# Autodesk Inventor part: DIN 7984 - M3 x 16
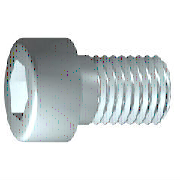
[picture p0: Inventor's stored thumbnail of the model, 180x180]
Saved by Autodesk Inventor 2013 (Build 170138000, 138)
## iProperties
Created: 2012-02
Part Number: DIN 7984 - M3 x 16
Material: Stahl, weich
Description: Zylinderkopfschraube
Document SubType Name: Modeling
Standard: DIN 7984
Designer: rYan
Standard Revision: 1985
Standards Organization: DIN
Language: de-DE
Size Designation: M3 x 16
Categories: <MemberInstance><Categories><Category DisplayName="Verbindungselemente" InternalName="e4da775c-781d-43d5-af7c-5136215cf5a6" Mnemonic="FSTN"><Category DisplayNam
Density: 7.86 g/cm^3
Mass: 1.20882 g
Surface Area: 2.39725 cm^2
Volume: 0.153794 cm^3
IsCustomPart: 0
Author: rYan
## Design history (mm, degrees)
sketch "Skizze1"
  geometry: L1 (0.167, 0)-(16, 0); L2 (16, 0)-(16, 1.5); L3 (16, 1.5)-(1.5, 1.5); L4 (1.5, 1.5)-(1.193, 1.5); L5 (1.193, 1.5)-(0, 1.5); L6 (0, 1.5)-(0, 2.75); L7 (0, 2.75)-(-2, 2.75); L8 (-2, 2.75)-(-2, 1.155); L9 (-2, 1.155)-(-0.5, 1.155); L10 (-0.5, 1.155)-(0.167, 0); L11 (-5.6, 0)-(19.6, 0) reference; L12 (0, -0.55)-(0, 3.3) reference; L13 (1.5, 1.5)-(0, 1.5)
  constraints: 22 end point, 6 parallel, 2 collinear, 2 perpendicular, 1 horizontal, 1 point on line
  dimensions: "d1" = 14.5 distance from line of L3.end L2 (= GEL); "d2" = 0.30683 distance of L4.end L3.end (computed from GAL); "d3" = 2 distance between parallel lines of L8 L6 (= KOH); "d4" = 1.5 distance of L8.end L9.end (= INTI); "d5" = 60 deg angle of L10 L1; "d6" = 3 diameter of L3 L1 (= GD); "d7" = 3 diameter of L5 L1 (= BDM); "d8" = 2.3094 diameter of L9 L1 (= 1.1547 x SW); "d9" = 5.5 diameter of L7 L1 (= KOD); "d26" = 16 distance between parallel lines of L12 L2 (= NLG)
revolve "Körper" sketch "Skizze1" stored, may be unused: angle "d10" = 90 deg
sketch "Skizze2"
  geometry: L1 (0, -3.85)-(0, 3.85) reference; L2 (-3.85, 0)-(3.85, 0) reference; L3 (1.155, 0)-(0.577, -1); L4 (0.577, -1)-(-0.577, -1); L5 (-0.577, -1)-(-1.155, 0); L6 (-1.155, 0)-(-0.577, 1); L7 (-0.577, 1)-(0.577, 1); L8 (0.577, 1)-(1.155, 0); 2 further points
  constraints: 12 end point, 1 coincident, 1 horizontal alignment, 1 point on line, 12 other
extrude "Loch" join sketch "Skizze2" stored distance "d11" = 10; taper "d12" = 0 deg
workplane "Work Plane1"
fillet "Fillet2" dims "d30" = 0.1 (= R)
body "Solid1"
fillet "Rundung1" dims "d17" = 0.3 (= RR)
feature "Gewinde" dims "d13" = 14.5 (= GEL), "d14" = 0
chamfer "Fase1" distance "d15" = 0.30673 (= -0.5 x SPD + 0.5 x GD); stored, may be unused: second distance "d16" = 0.30673 (= GUL), angle "d27" = 45 deg
other parameters: "GD" = 3 (= NND) [user parameter; used in 2 equation terms], "NLG" = 16 [user parameter; used in 1 equation term], "GEL" = 14.5 [user parameter; used in 2 equation terms], "KOD" = 5.5 [user parameter; used in 1 equation term], "KOH" = 2 [user parameter; used in 1 equation term], "INTI" = 1.5 [user parameter; used in 1 equation term], "GAL" = 0.30673 (= 0.61345 x PTC) [user parameter; used in 1 equation term], "GUL" = 0.30673 (= 0.61345 x PTC) [user parameter; used in 1 equation term], "BDM" = 3 (= NND) [user parameter; used in 1 equation term], "SW" = 2 [user parameter; used in 2 equation terms], "RR" = 0.3 [user parameter; used in 1 equation term], "SPD" = 2.38655 (= NND - 1.2269 x PTC) [user parameter; used in 1 equation term], "d19" = 0, "d28" = 0, "d29" = 0, "R" = 0.1 [user parameter; used in 1 equation term], "TOA" = 30 deg [user parameter], "GD1" = 2.38655 (= THREADDIA - 1.2269 x PTC) [user parameter], "THREADDIA" = 3 [user parameter; used in 1 equation term], "FAWI" = 45 deg [user parameter], "ANG" = 120 deg [user parameter], "PTC" = 0.5 [user parameter; used in 5 equation terms], "NND" = 3 [user parameter; used in 3 equation terms], "E0" = 2.31 (= 1.155 x SW) [user parameter]
